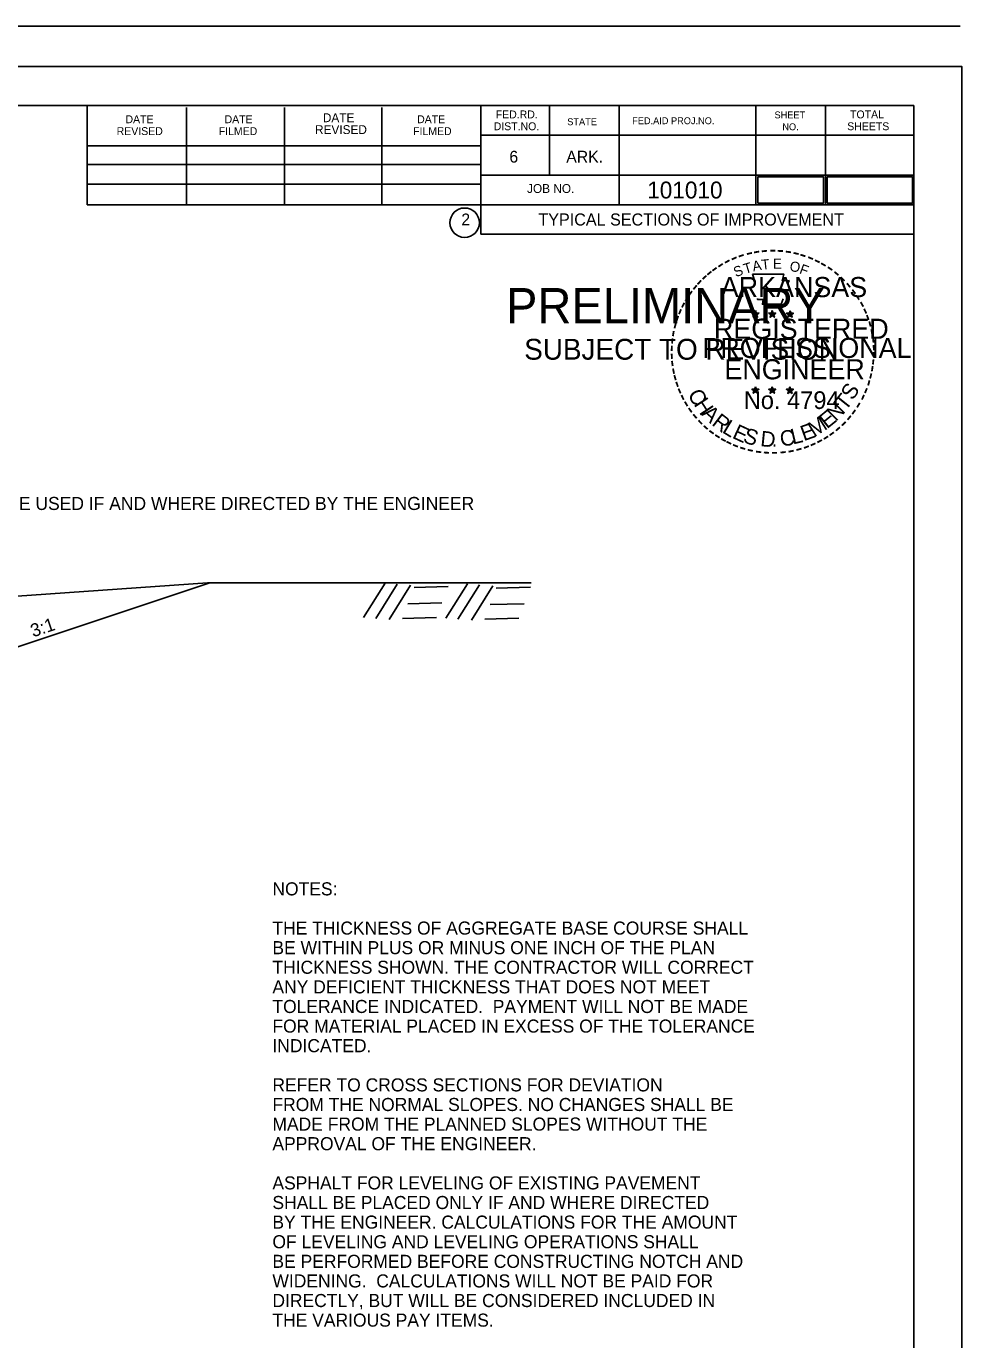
# Model space of a CAD drawing. Extents: x 1373719 to 1374161, y 379835 to 380167.
# Drawn here: x 1373999.9 to 1374046.4, y 380076.3 to 380141.6 of the extents above; entities that cross this region are included whole.
import ezdxf

# ---------------------------------------------------------------- set-up
doc = ezdxf.new("R2010")
doc.units = 0
for name, color, linetype in [('DATE', 7, 'Continuous'), ('GREEN_TXT', 7, 'Continuous'), ('Ground Hatch', 7, 'Continuous'), ('Page Number', 7, 'Continuous'), ('Pavement Layers', 7, 'Continuous'), ('R_Border Notes', 7, 'Continuous'), ('R_Border Prem', 7, 'Continuous'), ('R_NoPlot', 7, 'Continuous'), ('R_Stamp', 7, 'Continuous'), ('T_Drafting', 7, 'Continuous'), ('Total Pages', 7, 'Continuous')]:
    doc.layers.add(name, color=color, linetype=linetype)

msp = doc.modelspace()

# ---------------------------------------------------------------- linework, layer by layer
msp.add_line((1373996.075, 380109.635), (1374008.976, 380113.935))
at = {"layer": 'DATE'}
for p, q in [((1374046.363, 380141.63), (1373870.363, 380141.63)), ((1373885.973, 380137.69), (1374044.063, 380137.69)), ((1374002.933, 380132.75), (1374002.933, 380137.69)), ((1374007.863, 380132.75), (1374007.863, 380137.59)), ((1374012.743, 380132.75), (1374012.743, 380137.59)), ((1374017.583, 380132.75), (1374017.583, 380137.59)), ((1374022.513, 380137.69), (1374022.513, 380131.29)), ((1374025.933, 380137.69), (1374025.933, 380134.22)), ((1374029.403, 380137.69), (1374029.403, 380132.75)), ((1374036.193, 380137.69), (1374036.193, 380132.75)), ((1374039.663, 380137.69), (1374039.663, 380132.75)), ((1374044.063, 380034.96), (1374044.063, 380137.69)), ((1374044.063, 380136.22), (1374022.513, 380136.22)), ((1374044.063, 380136.23), (1374044.063, 380136.23)), ((1374002.933, 380135.68), (1374022.513, 380135.68)), ((1374002.933, 380134.75), (1374022.513, 380134.75)), ((1374044.063, 380134.22), (1374022.513, 380134.22)), ((1374002.933, 380133.78), (1374022.513, 380133.78)), ((1374044.063, 380132.75), (1374002.933, 380132.75)), ((1374022.513, 380131.29), (1374044.063, 380131.29))]:
    msp.add_line(p, q, dxfattribs=at)
msp.add_circle((1374021.706, 380131.858), 0.733, dxfattribs=at)
at = {"layer": 'Ground Hatch'}
for p, q in [((1374016.682, 380112.227), (1374017.749, 380113.935)), ((1374017.282, 380112.178), (1374018.349, 380113.886)), ((1374017.951, 380112.132), (1374019.019, 380113.84)), ((1374020.774, 380112.189), (1374021.841, 380113.896)), ((1374021.374, 380112.14), (1374022.441, 380113.848)), ((1374022.043, 380112.094), (1374023.111, 380113.802)), ((1374019.19, 380113.72), (1374020.886, 380113.766)), ((1374023.282, 380113.682), (1374024.977, 380113.728)), ((1374018.884, 380112.902), (1374020.58, 380112.948)), ((1374022.976, 380112.864), (1374024.672, 380112.91)), ((1374018.617, 380112.183), (1374020.313, 380112.229)), ((1374022.709, 380112.145), (1374024.405, 380112.19))]:
    msp.add_line(p, q, dxfattribs=at)
at = {"layer": 'Page Number'}
msp.add_lwpolyline([(1374036.295, 380132.825), (1374039.56, 380132.825), (1374039.56, 380134.145), (1374036.295, 380134.145)], close=True, dxfattribs=at)
at = {"layer": 'R_NoPlot'}
msp.add_lwpolyline([(1373879.769, 380139.637), (1374046.439, 380139.637), (1374046.439, 380032.969), (1373879.769, 380032.969)], close=True, dxfattribs=at)
at = {"layer": 'R_Stamp'}
for p, q in [((1374036.003, 380127.364), (1374036.178, 380127.309)), ((1374036.003, 380127.364), (1374036.13, 380127.342)), ((1374036.003, 380127.364), (1374036.122, 380127.303)), ((1374036.07, 380127.16), (1374036.178, 380127.309)), ((1374036.07, 380127.16), (1374036.133, 380127.282)), ((1374036.07, 380127.16), (1374036.177, 380127.269)), ((1374036.178, 380127.491), (1374036.157, 380127.365)), ((1374036.284, 380127.16), (1374036.177, 380127.267)), ((1374036.178, 380127.309), (1374036.178, 380127.491)), ((1374036.178, 380127.491), (1374036.202, 380127.366)), ((1374036.351, 380127.364), (1374036.178, 380127.309)), ((1374036.284, 380127.16), (1374036.178, 380127.309)), ((1374036.351, 380127.364), (1374036.208, 380127.34)), ((1374036.284, 380127.16), (1374036.216, 380127.306)), ((1374036.351, 380127.364), (1374036.249, 380127.313)), ((1374036.838, 380127.364), (1374037.013, 380127.309)), ((1374036.838, 380127.364), (1374036.965, 380127.342)), ((1374036.838, 380127.364), (1374036.957, 380127.303)), ((1374036.905, 380127.16), (1374037.013, 380127.309)), ((1374036.905, 380127.16), (1374036.968, 380127.282)), ((1374036.905, 380127.16), (1374037.012, 380127.269)), ((1374037.013, 380127.491), (1374036.992, 380127.365)), ((1374037.119, 380127.16), (1374037.012, 380127.267)), ((1374037.013, 380127.309), (1374037.013, 380127.491)), ((1374037.013, 380127.491), (1374037.037, 380127.366)), ((1374037.186, 380127.364), (1374037.013, 380127.309)), ((1374037.119, 380127.16), (1374037.013, 380127.309)), ((1374037.186, 380127.364), (1374037.043, 380127.34)), ((1374037.119, 380127.16), (1374037.051, 380127.306)), ((1374037.186, 380127.364), (1374037.084, 380127.313)), ((1374037.72, 380127.358), (1374037.895, 380127.303)), ((1374037.72, 380127.358), (1374037.847, 380127.336)), ((1374037.72, 380127.358), (1374037.839, 380127.297)), ((1374037.787, 380127.154), (1374037.895, 380127.303)), ((1374037.787, 380127.154), (1374037.85, 380127.276)), ((1374037.787, 380127.154), (1374037.894, 380127.263)), ((1374037.895, 380127.485), (1374037.874, 380127.359)), ((1374038.001, 380127.154), (1374037.894, 380127.261)), ((1374037.895, 380127.303), (1374037.895, 380127.485)), ((1374037.895, 380127.485), (1374037.919, 380127.36)), ((1374038.068, 380127.358), (1374037.895, 380127.303)), ((1374038.001, 380127.154), (1374037.895, 380127.303)), ((1374038.068, 380127.358), (1374037.925, 380127.334)), ((1374038.001, 380127.154), (1374037.933, 380127.3)), ((1374038.068, 380127.358), (1374037.966, 380127.307)), ((1374036.176, 380123.705), (1374036.155, 380123.579)), ((1374036.176, 380123.522), (1374036.176, 380123.705)), ((1374036.176, 380123.705), (1374036.2, 380123.58)), ((1374037.01, 380123.705), (1374036.99, 380123.579)), ((1374037.01, 380123.522), (1374037.01, 380123.705)), ((1374037.01, 380123.705), (1374037.035, 380123.58)), ((1374037.894, 380123.7), (1374037.873, 380123.574)), ((1374037.894, 380123.517), (1374037.894, 380123.7)), ((1374037.894, 380123.7), (1374037.918, 380123.575)), ((1374036.001, 380123.578), (1374036.176, 380123.522)), ((1374036.001, 380123.578), (1374036.128, 380123.555)), ((1374036.001, 380123.578), (1374036.12, 380123.517)), ((1374036.068, 380123.374), (1374036.176, 380123.522)), ((1374036.068, 380123.374), (1374036.131, 380123.496)), ((1374036.068, 380123.374), (1374036.175, 380123.482)), ((1374036.282, 380123.374), (1374036.175, 380123.481)), ((1374036.349, 380123.578), (1374036.176, 380123.522)), ((1374036.282, 380123.374), (1374036.176, 380123.522)), ((1374036.349, 380123.578), (1374036.206, 380123.553)), ((1374036.282, 380123.374), (1374036.214, 380123.519)), ((1374036.349, 380123.578), (1374036.247, 380123.527)), ((1374036.836, 380123.578), (1374037.01, 380123.522)), ((1374036.836, 380123.578), (1374036.962, 380123.555)), ((1374036.836, 380123.578), (1374036.954, 380123.517)), ((1374036.902, 380123.374), (1374037.01, 380123.522)), ((1374036.902, 380123.374), (1374036.965, 380123.496)), ((1374036.902, 380123.374), (1374037.009, 380123.482)), ((1374037.117, 380123.374), (1374037.009, 380123.481)), ((1374037.184, 380123.578), (1374037.01, 380123.522)), ((1374037.117, 380123.374), (1374037.01, 380123.522)), ((1374037.184, 380123.578), (1374037.041, 380123.553)), ((1374037.117, 380123.374), (1374037.048, 380123.519)), ((1374037.184, 380123.578), (1374037.082, 380123.527)), ((1374037.719, 380123.573), (1374037.894, 380123.517)), ((1374037.719, 380123.573), (1374037.846, 380123.55)), ((1374037.719, 380123.573), (1374037.838, 380123.512)), ((1374037.786, 380123.369), (1374037.894, 380123.517)), ((1374037.786, 380123.369), (1374037.849, 380123.491)), ((1374037.786, 380123.369), (1374037.893, 380123.477)), ((1374038, 380123.369), (1374037.893, 380123.476)), ((1374038.067, 380123.573), (1374037.894, 380123.517)), ((1374038, 380123.369), (1374037.894, 380123.517)), ((1374038.067, 380123.573), (1374037.924, 380123.548)), ((1374038, 380123.369), (1374037.932, 380123.514)), ((1374038.067, 380123.573), (1374037.965, 380123.522))]:
    msp.add_line(p, q, dxfattribs=at)
for points in [[(1374036.024, 380129.303), (1374036.158, 380128.89)], [(1374037.779, 380128.842), (1374037.85, 380128.984), (1374037.508, 380128.972), (1374037.582, 380129.303), (1374036.024, 380129.303)], [(1374036.27, 380128.092), (1374036.27, 380128.048), (1374036.551, 380128.039), (1374036.524, 380127.802), (1374037.459, 380127.802), (1374037.56, 380128.07)], [(1374036.178, 380127.491), (1374036.284, 380127.16), (1374036.003, 380127.364), (1374036.351, 380127.364), (1374036.07, 380127.16), (1374036.178, 380127.491)], [(1374037.013, 380127.491), (1374037.119, 380127.16), (1374036.838, 380127.364), (1374037.186, 380127.364), (1374036.905, 380127.16), (1374037.013, 380127.491)], [(1374037.895, 380127.485), (1374038.001, 380127.154), (1374037.72, 380127.358), (1374038.068, 380127.358), (1374037.787, 380127.154), (1374037.895, 380127.485)], [(1374036.176, 380123.705), (1374036.282, 380123.374), (1374036.001, 380123.578), (1374036.349, 380123.578), (1374036.068, 380123.374), (1374036.176, 380123.705)], [(1374037.01, 380123.705), (1374037.117, 380123.374), (1374036.836, 380123.578), (1374037.184, 380123.578), (1374036.902, 380123.374), (1374037.01, 380123.705)], [(1374037.894, 380123.7), (1374038, 380123.369), (1374037.719, 380123.573), (1374038.067, 380123.573), (1374037.786, 380123.369), (1374037.894, 380123.7)]]:
    msp.add_lwpolyline(points, dxfattribs=at)
for centre, radius in [((1374036.177, 380127.308), 0.0861), ((1374036.177, 380127.308), 0.0723), ((1374036.177, 380127.308), 0.0579), ((1374036.177, 380127.308), 0.0495), ((1374036.177, 380127.308), 0.0374), ((1374036.177, 380127.308), 0.0248), ((1374036.177, 380127.308), 0.0148), ((1374037.012, 380127.308), 0.0861), ((1374037.012, 380127.308), 0.0723), ((1374037.012, 380127.308), 0.0579), ((1374037.012, 380127.308), 0.0495), ((1374037.012, 380127.308), 0.0374), ((1374037.012, 380127.308), 0.0248), ((1374037.012, 380127.308), 0.0148), ((1374037.894, 380127.302), 0.0861), ((1374037.894, 380127.302), 0.0723), ((1374037.894, 380127.302), 0.0579), ((1374037.894, 380127.302), 0.0495), ((1374037.894, 380127.302), 0.0374), ((1374037.894, 380127.302), 0.0248), ((1374037.894, 380127.302), 0.0148), ((1374036.175, 380123.522), 0.0861), ((1374036.175, 380123.522), 0.0723), ((1374036.175, 380123.522), 0.0579), ((1374037.01, 380123.522), 0.0861), ((1374037.01, 380123.522), 0.0723), ((1374037.01, 380123.522), 0.0579), ((1374037.893, 380123.517), 0.0861), ((1374037.893, 380123.517), 0.0723), ((1374036.175, 380123.522), 0.0495), ((1374036.175, 380123.522), 0.0374), ((1374036.175, 380123.522), 0.0248), ((1374036.175, 380123.522), 0.0148), ((1374037.01, 380123.522), 0.0495), ((1374037.01, 380123.522), 0.0374), ((1374037.01, 380123.522), 0.0248), ((1374037.01, 380123.522), 0.0148), ((1374037.893, 380123.517), 0.0579), ((1374037.893, 380123.517), 0.0495), ((1374037.893, 380123.517), 0.0374), ((1374037.893, 380123.517), 0.0248), ((1374037.893, 380123.517), 0.0148)]:
    msp.add_circle(centre, radius, dxfattribs=at)
at = {"layer": 'T_Drafting'}
msp.add_lwpolyline([(1373907.987, 380106.564), (1373924.533, 380106.487), (1373943.45, 380108.654), (1373953.585, 380112.614), (1373955.026, 380112.615), (1373964.851, 380112.903), (1373975.028, 380112.689), (1373976.603, 380112.615), (1373985.688, 380110.353), (1373993.989, 380112.909), (1374008.917, 380113.95), (1374025.023, 380113.95)], dxfattribs=at)
at = {"layer": 'Total Pages'}
msp.add_lwpolyline([(1374039.745, 380132.825), (1374043.981, 380132.825), (1374043.981, 380134.145), (1374039.745, 380134.145)], close=True, dxfattribs=at)

# ---------------------------------------------------------------- texts
at = {"layer": 'DATE'}
for s, height, p in [('DATE', 0.4396, (1374014.653, 380136.86)), ('FED.RD.', 0.391, (1374023.253, 380137.05)), ('SHEET', 0.342, (1374037.123, 380137.05)), ('TOTAL', 0.391, (1374040.883, 380137.05)), ('DATE', 0.391, (1374004.833, 380136.81)), ('DATE', 0.391, (1374009.763, 380136.81)), ('REVISED', 0.4396, (1374014.263, 380136.27)), ('DATE', 0.391, (1374019.343, 380136.81)), ('DIST.NO.', 0.391, (1374023.153, 380136.46)), ('STATE', 0.342, (1374026.813, 380136.71)), ('FED.AID PROJ.NO.', 0.342, (1374030.043, 380136.76)), ('NO.', 0.342, (1374037.513, 380136.46)), ('SHEETS', 0.391, (1374040.743, 380136.46)), ('REVISED', 0.391, (1374004.393, 380136.22)), ('FILMED', 0.391, (1374009.473, 380136.22)), ('FILMED', 0.391, (1374019.143, 380136.22)), ('6', 0.586, (1374023.933, 380134.85)), ('ARK.', 0.5861, (1374026.763, 380134.85)), ('JOB NO.', 0.4396, (1374024.813, 380133.34)), ('2', 0.586, (1374021.543, 380131.73))]:
    msp.add_text(s, height=height, dxfattribs=at).set_placement(p)
at = {"layer": 'GREEN_TXT'}
msp.add_text('3:1', height=0.65, rotation=18.47817, dxfattribs=at).set_placement((1374000.236, 380111.236))
for s, p in [('NOTES: ', (1374012.143, 380098.404)), ('THE THICKNESS OF AGGREGATE BASE COURSE SHALL', (1374012.143, 380096.454)), ('BE WITHIN PLUS OR MINUS ONE INCH OF THE PLAN', (1374012.143, 380095.479)), ('THICKNESS SHOWN. THE CONTRACTOR WILL CORRECT', (1374012.143, 380094.504)), ('ANY DEFICIENT THICKNESS THAT DOES NOT MEET', (1374012.143, 380093.529)), ('TOLERANCE INDICATED.  PAYMENT WILL NOT BE MADE', (1374012.143, 380092.554)), ('FOR MATERIAL PLACED IN EXCESS OF THE TOLERANCE', (1374012.143, 380091.579)), ('INDICATED.', (1374012.143, 380090.604)), ('REFER TO CROSS SECTIONS FOR DEVIATION', (1374012.143, 380088.654)), ('FROM THE NORMAL SLOPES. NO CHANGES SHALL BE', (1374012.143, 380087.679)), ('MADE FROM THE PLANNED SLOPES WITHOUT THE ', (1374012.143, 380086.704)), ('APPROVAL OF THE ENGINEER.', (1374012.143, 380085.729)), ('ASPHALT FOR LEVELING OF EXISTING PAVEMENT', (1374012.143, 380083.779)), ('SHALL BE PLACED ONLY IF AND WHERE DIRECTED ', (1374012.143, 380082.804)), ('BY THE ENGINEER. CALCULATIONS FOR THE AMOUNT', (1374012.143, 380081.829)), ('OF LEVELING AND LEVELING OPERATIONS SHALL', (1374012.143, 380080.854)), ('BE PERFORMED BEFORE CONSTRUCTING NOTCH AND ', (1374012.143, 380079.879)), ('WIDENING.  CALCULATIONS WILL NOT BE PAID FOR', (1374012.143, 380078.904)), ('DIRECTLY, BUT WILL BE CONSIDERED INCLUDED IN', (1374012.143, 380077.929)), ('THE VARIOUS PAY ITEMS.    ', (1374012.143, 380076.954))]:
    msp.add_text(s, height=0.65, dxfattribs=at).set_placement(p)
at = {"layer": 'Pavement Layers'}
msp.add_text('* TO BE USED IF AND WHERE DIRECTED BY THE ENGINEER', height=0.65, dxfattribs=at).set_placement((1373996.924, 380117.571))
at = {"layer": 'R_Border Notes'}
for s, height, p in [('101010', 0.84, (1374030.79, 380133.065)), ('TYPICAL SECTIONS OF IMPROVEMENT', 0.6, (1374025.375, 380131.72))]:
    msp.add_text(s, height=height, dxfattribs=at).set_placement(p)
at = {"layer": 'R_Border Prem'}
for s, height, p in [('PRELIMINARY', 1.75, (1374023.766, 380126.861)), ('SUBJECT TO REVISION', 1.03756, (1374024.67, 380125.046))]:
    msp.add_text(s, height=height, dxfattribs=at).set_placement(p)
at = {"layer": 'R_Stamp'}
for s, height, rotation, p in [('-', 0.8, 24.30721, (1374035.081, 380129.732)), ('-', 0.8, 19.17608, (1374035.398, 380129.867)), ('-', 0.8, 13.63015, (1374035.773, 380129.987)), ('-', 0.8, 10.21935, (1374036.112, 380130.068)), ('-', 0.8, 5.89682, (1374036.476, 380130.123)), ('-', 0.8, 0.18623, (1374036.862, 380130.159)), ('-', 0.8, 357.74304, (1374037.224, 380130.153)), ('-', 0.8, 352.16172, (1374037.596, 380130.125)), ('-', 0.8, 347.20489, (1374037.955, 380130.068)), ('-', 0.8, 342.3362, (1374038.273, 380129.99)), ('-', 0.8, 337.85509, (1374038.64, 380129.879)), ('-', 0.8, 38.95066, (1374033.939, 380129.002)), ('-', 0.8, 36.23174, (1374034.177, 380129.191)), ('-', 0.8, 34.06357, (1374034.466, 380129.389)), ('-', 0.8, 28.79182, (1374034.764, 380129.574)), ('S', 0.5, 21.59401, (1374035.201, 380129.142)), ('T', 0.5, 16.4036, (1374035.658, 380129.308)), ('A', 0.5, 11.21318, (1374036.071, 380129.433)), ('T', 0.5, 6.02276, (1374036.496, 380129.516)), ('E', 0.5, 0.83234, (1374037.048, 380129.571)), ('O', 0.5, 350.4515, (1374037.85, 380129.466)), ('F', 0.5, 340.07066, (1374038.327, 380129.352)), ('-', 0.8, 334.12109, (1374038.956, 380129.743)), ('-', 0.8, 329.64089, (1374039.245, 380129.602)), ('-', 0.8, 325.86266, (1374039.567, 380129.421)), ('-', 0.8, 48.42305, (1374033.498, 380128.555)), ('-', 0.8, 42.96224, (1374033.722, 380128.794)), ('-', 0.8, 320.52971, (1374039.872, 380129.208)), ('-', 0.8, 315.57859, (1374040.171, 380128.964)), ('-', 0.8, 309.87973, (1374040.456, 380128.689)), ('-', 0.8, 58.07063, (1374032.928, 380127.765)), ('-', 0.8, 54.23247, (1374033.09, 380128.028)), ('-', 0.8, 50.61418, (1374033.297, 380128.312)), ('-', 0.8, 306.65218, (1374040.718, 380128.388)), ('-', 0.7, 303.67529, (1374040.961, 380128.104)), ('-', 0.8, 67.77427, (1374032.642, 380127.152)), ('-', 0.8, 62.87135, (1374032.771, 380127.458)), ('-', 0.8, 299.66835, (1374041.121, 380127.801)), ('-', 0.8, 294.66279, (1374041.283, 380127.495)), ('-', 0.8, 75.46096, (1374032.434, 380126.48)), ('-', 0.8, 72.39447, (1374032.532, 380126.837)), ('-', 0.8, 290.57283, (1374041.411, 380127.206)), ('-', 0.8, 285.12326, (1374041.528, 380126.916)), ('-', 0.8, 81.20126, (1374032.368, 380126.124)), ('-', 0.8, 280.54934, (1374041.628, 380126.545)), ('-', 0.8, 89.06224, (1374032.317, 380125.428)), ('-', 0.8, 85.18634, (1374032.33, 380125.778)), ('-', 0.8, 276.59616, (1374041.709, 380126.161)), ('-', 0.8, 274.33011, (1374041.739, 380125.8)), ('-', 0.8, 94.19588, (1374032.335, 380125.065)), ('-', 0.8, 98.94793, (1374032.371, 380124.732)), ('-', 0.8, 263.5172, (1374041.747, 380125.151)), ('-', 0.8, 269.94067, (1374041.756, 380125.484)), ('-', 0.8, 101.71495, (1374032.438, 380124.365)), ('-', 0.8, 105.45785, (1374032.519, 380124.068)), ('-', 0.8, 255.7626, (1374041.656, 380124.485)), ('-', 0.8, 260.99529, (1374041.711, 380124.824)), ('-', 0.8, 109.08742, (1374032.627, 380123.752)), ('-', 0.8, 114.06432, (1374032.754, 380123.454)), ('S', 0.77, 57.878, (1374041.022, 380122.988)), ('-', 0.8, 247.88866, (1374041.454, 380123.789)), ('-', 0.8, 255.7626, (1374041.56, 380124.141)), ('-', 0.8, 115.72885, (1374032.906, 380123.145)), ('-', 0.8, 120.44712, (1374033.085, 380122.852)), ('C', 0.77, 296.9133, (1374032.79, 380123.35)), ('H', 0.77, 303.27986, (1374033.086, 380122.83)), ('N', 0.77, 45.14487, (1374040.177, 380121.946)), ('T', 0.77, 51.51144, (1374040.657, 380122.467)), ('-', 0.8, 244.61971, (1374041.323, 380123.474)), ('-', 0.8, 125.89344, (1374033.286, 380122.572)), ('-', 0.8, 130.71812, (1374033.517, 380122.296)), ('A', 0.77, 316.01299, (1374033.45, 380122.317)), ('R', 0.77, 322.37955, (1374033.962, 380121.826)), ('E', 0.77, 38.77831, (1374039.733, 380121.581)), ('-', 0.8, 231.25377, (1374040.71, 380122.489)), ('-', 0.8, 233.84524, (1374040.925, 380122.772)), ('-', 0.8, 239.07125, (1374041.126, 380123.098)), ('-', 0.8, 134.22381, (1374033.776, 380122.023)), ('-', 0.8, 138.93382, (1374034.038, 380121.791)), ('L', 0.77, 328.74612, (1374034.476, 380121.451)), ('E', 0.77, 335.11268, (1374034.978, 380121.172)), ('S', 0.77, 341.47924, (1374035.511, 380120.956)), ('E', 0.77, 19.67862, (1374038.581, 380120.986)), ('M', 0.77, 32.41175, (1374039.093, 380121.175)), ('-', 0.8, 221.08509, (1374040.21, 380121.952)), ('-', 0.8, 225.76533, (1374040.471, 380122.207)), ('-', 0.8, 144.64634, (1374034.316, 380121.588)), ('-', 0.8, 148.08978, (1374034.597, 380121.403)), ('-', 0.8, 151.57039, (1374034.886, 380121.24)), ('-', 0.8, 154.60019, (1374035.147, 380121.117)), ('D', 0.77, 354.21237, (1374036.395, 380120.75)), ('C', 0.77, 6.94549, (1374037.438, 380120.731)), ('L', 0.77, 13.31206, (1374038.03, 380120.826)), ('-', 0.8, 207.35684, (1374039.389, 380121.35)), ('-', 0.8, 212.24909, (1374039.668, 380121.523)), ('-', 0.8, 215.73633, (1374039.935, 380121.716)), ('-', 0.8, 158.56121, (1374035.459, 380120.99)), ('-', 0.8, 162.79826, (1374035.803, 380120.883)), ('-', 0.8, 167.55551, (1374036.16, 380120.801)), ('-', 0.8, 173.11546, (1374036.546, 380120.746)), ('-', 0.8, 176.51827, (1374036.92, 380120.72)), ('-', 0.8, 181.59176, (1374037.292, 380120.729)), ('.', 0.77, 0.57893, (1374036.981, 380120.712)), ('-', 0.8, 185.81666, (1374037.697, 380120.767)), ('-', 0.8, 191.28576, (1374038.065, 380120.833)), ('-', 0.8, 195.47429, (1374038.429, 380120.933)), ('-', 0.8, 200.71842, (1374038.768, 380121.054)), ('-', 0.8, 204.25161, (1374039.077, 380121.19))]:
    msp.add_text(s, height=height, rotation=rotation, dxfattribs=at).set_placement(p)
for s, height, p in [('ARKANSAS', 1, (1374034.45, 380128.159)), ('REGISTERED', 1, (1374034.111, 380126.085)), ('PROFESSIONAL', 1, (1374033.537, 380125.133)), ('ENGINEER', 1, (1374034.631, 380124.07)), ('No. 4794', 0.8785, (1374035.593, 380122.595))]:
    msp.add_text(s, height=height, dxfattribs=at).set_placement(p)

doc.saveas('drawing.dxf')
